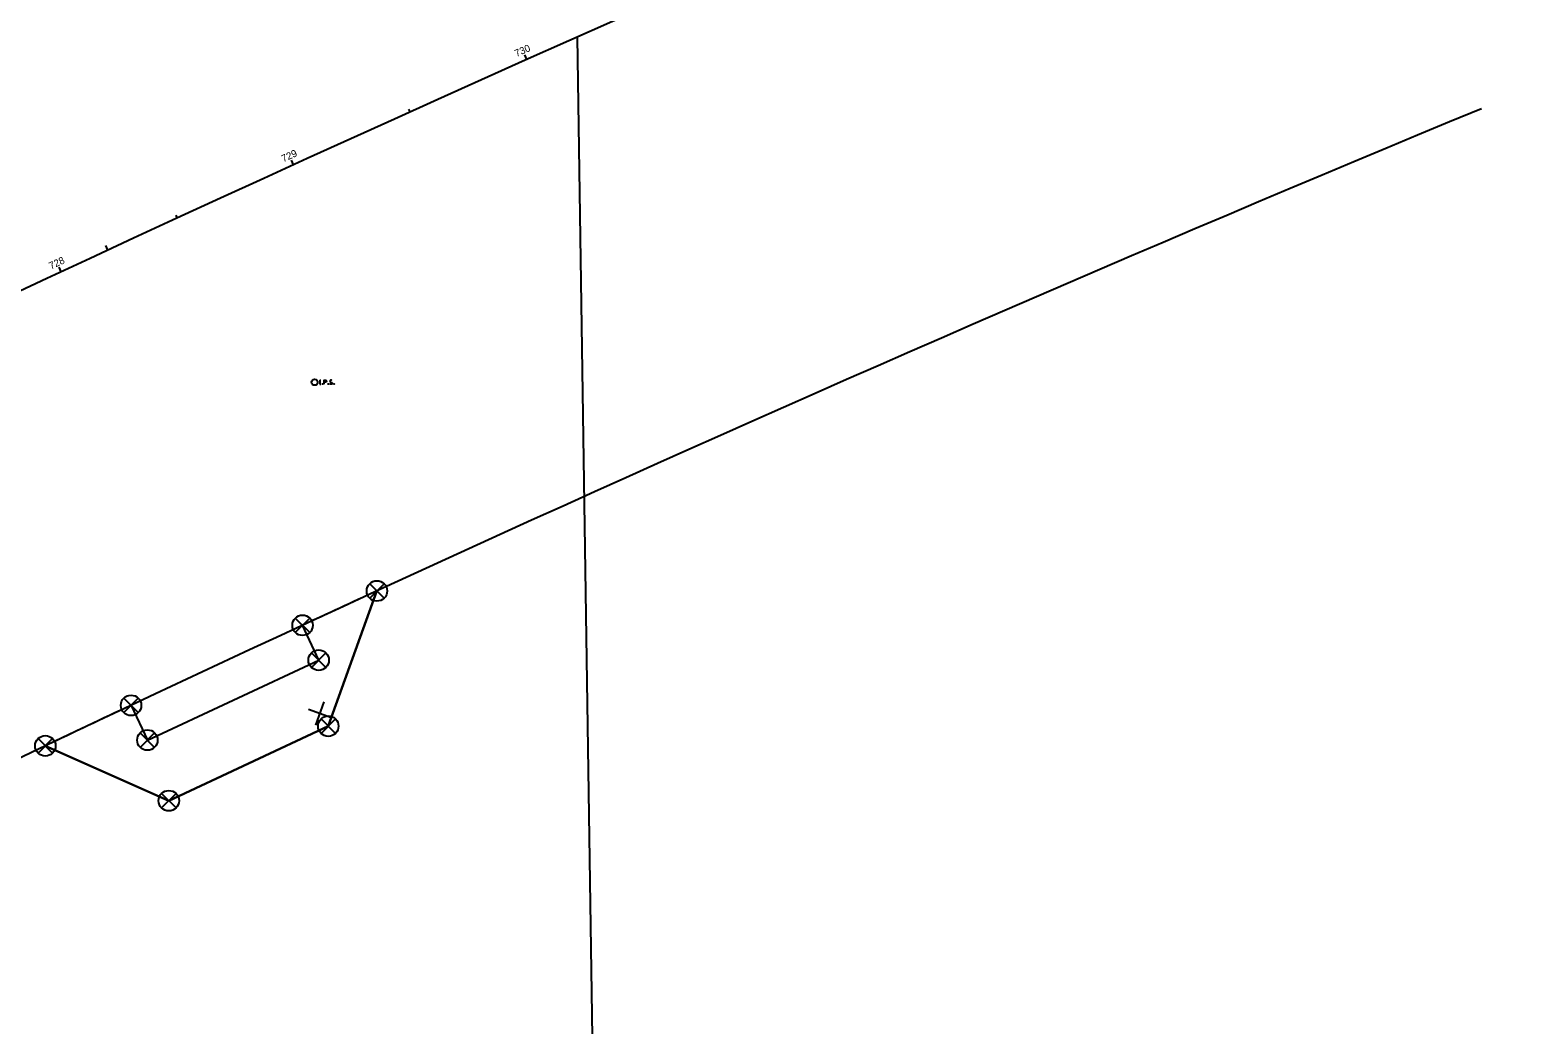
# Model space of a CAD drawing. Extents: x 197895 to 201888, y 454260 to 456995.
# Drawn here: x 201279 to 201868, y 456346 to 456735 of the extents above; entities that cross this region are included whole.
import ezdxf

# ---------------------------------------------------------------- set-up
doc = ezdxf.new("R2010")
doc.units = 0
for name, color, linetype in [('Default', 7, 'Continuous'), ('PF_P_Grade_Line', 7, 'Continuous'), ('PF_X_Ground_Line', 7, 'Continuous'), ('PV_X_EOP', 7, 'Continuous'), ('RD_X_GR_Rt', 7, 'Continuous'), ('RW_X_CL_100_Stations', 7, 'Continuous'), ('RW_X_Esmt_CH', 7, 'Continuous'), ('SC_Scratch1', 7, 'Continuous'), ('SH_Text', 7, 'Continuous'), ('SV_X_Void_Area', 7, 'Continuous'), ('VG_P_Text', 7, 'Continuous')]:
    doc.layers.add(name, color=color, linetype=linetype)

msp = doc.modelspace()

# ---------------------------------------------------------------- linework, layer by layer
at = {"layer": 'Default'}
for p, q in [((201308.11, 456650.4), (201308.96, 456648.59)), ((201411.39, 456518.27), (201417.05, 456512.61)), ((201411.39, 456512.61), (201417.05, 456518.27)), ((201414.22, 456515.44), (201414.22, 456515.44)), ((201382.33, 456504.86), (201387.99, 456499.2)), ((201382.33, 456499.2), (201387.99, 456504.86)), ((201385.16, 456502.03), (201385.16, 456502.03)), ((201388.63, 456491.25), (201394.29, 456485.59)), ((201388.63, 456485.59), (201394.29, 456491.25)), ((201391.46, 456488.42), (201391.46, 456488.42)), ((201315.28, 456473.56), (201320.94, 456467.9)), ((201315.28, 456467.9), (201320.94, 456473.56)), ((201318.11, 456470.73), (201318.11, 456470.73)), ((201392.39, 456465.43), (201398.05, 456459.78)), ((201392.39, 456459.78), (201398.05, 456465.43)), ((201395.22, 456462.61), (201395.22, 456462.61)), ((201281.78, 456457.73), (201287.43, 456452.08)), ((201281.78, 456452.08), (201287.43, 456457.73)), ((201321.67, 456459.99), (201327.33, 456454.33)), ((201321.67, 456454.33), (201327.33, 456459.99)), ((201324.5, 456457.16), (201324.5, 456457.16)), ((201284.61, 456454.9), (201284.61, 456454.9)), ((201330.04, 456436.29), (201335.69, 456430.64)), ((201330.04, 456430.64), (201335.69, 456436.29)), ((201332.86, 456433.47), (201332.86, 456433.47))]:
    msp.add_line(p, q, dxfattribs=at)
for centre in [(201414.22, 456515.44), (201385.16, 456502.03), (201391.46, 456488.42), (201318.11, 456470.73), (201324.5, 456457.16), (201395.22, 456462.61), (201284.61, 456454.9), (201332.86, 456433.47)]:
    msp.add_circle(centre, 4, dxfattribs=at)
at = {"layer": 'PF_P_Grade_Line'}
msp.add_circle((201284.61, 456454.9), 0.05, dxfattribs=at)
at = {"layer": 'PF_X_Ground_Line'}
for points in [[(201391.88, 456597.81), (201392.24, 456597.81)], [(201392.06, 456596.21), (201392.06, 456597.81)], [(201393.02, 456596.42), (201393.07, 456596.42), (201393.11, 456596.4), (201393.14, 456596.35), (201393.14, 456596.28), (201393.11, 456596.23), (201393.07, 456596.21), (201393.02, 456596.21), (201392.98, 456596.23), (201392.95, 456596.28), (201392.95, 456596.35), (201392.98, 456596.4), (201393.02, 456596.42)], [(201393.62, 456596.21), (201393.62, 456597.81), (201394.15, 456597.81), (201394.21, 456597.79), (201394.29, 456597.77), (201394.32, 456597.74), (201394.35, 456597.72), (201394.4, 456597.66), (201394.43, 456597.59), (201394.45, 456597.49), (201394.45, 456597.34), (201394.44, 456597.29), (201394.42, 456597.22), (201394.37, 456597.13), (201394.33, 456597.09), (201394.3, 456597.06), (201394.24, 456597.04), (201394.15, 456597.03), (201393.62, 456597.03)], [(201395.27, 456596.42), (201395.32, 456596.42), (201395.35, 456596.4), (201395.39, 456596.35), (201395.39, 456596.28), (201395.35, 456596.23), (201395.32, 456596.21), (201395.27, 456596.21), (201395.23, 456596.23), (201395.2, 456596.28), (201395.2, 456596.35), (201395.23, 456596.4), (201395.27, 456596.42)], [(201396.63, 456597.69), (201396.61, 456597.72), (201396.58, 456597.74), (201396.48, 456597.78), (201396.36, 456597.81), (201396.27, 456597.81), (201396.24, 456597.81), (201396.09, 456597.77), (201395.97, 456597.69), (201395.89, 456597.59), (201395.87, 456597.49), (201395.87, 456597.42), (201395.89, 456597.32), (201395.98, 456597.23), (201396.59, 456596.85), (201396.64, 456596.8), (201396.67, 456596.75), (201396.69, 456596.67), (201396.69, 456596.6), (201396.68, 456596.52), (201396.67, 456596.47), (201396.64, 456596.41), (201396.62, 456596.36), (201396.6, 456596.32), (201396.57, 456596.28), (201396.53, 456596.26), (201396.49, 456596.23), (201396.46, 456596.22), (201396.36, 456596.21), (201396.2, 456596.21), (201396.1, 456596.23), (201395.96, 456596.32), (201395.87, 456596.4)], [(201397.45, 456596.42), (201397.5, 456596.42), (201397.54, 456596.4), (201397.57, 456596.35), (201397.57, 456596.28), (201397.54, 456596.23), (201397.5, 456596.21), (201397.45, 456596.21), (201397.42, 456596.23), (201397.38, 456596.28), (201397.38, 456596.35), (201397.42, 456596.4), (201397.45, 456596.42)], [(201391.88, 456596.21), (201392.24, 456596.21)]]:
    msp.add_lwpolyline(points, dxfattribs=at)
msp.add_circle((201389.86, 456597.01), 1.2, dxfattribs=at)
at = {"layer": 'PV_X_EOP'}
msp.add_line((201492.53, 456731.9), (201504.39, 455930.45), dxfattribs=at)
at = {"layer": 'RD_X_GR_Rt'}
for p, q in [((201414.22, 456515.44), (201395.22, 456462.61)), ((201391.46, 456488.42), (201385.16, 456502.03)), ((201324.5, 456457.16), (201391.46, 456488.42)), ((201318.11, 456470.73), (201324.5, 456457.16)), ((201395.22, 456462.61), (201332.86, 456433.47)), ((201332.86, 456433.47), (201284.61, 456454.9))]:
    msp.add_line(p, q, dxfattribs=at)
for start, end in [(114.697117, 114.848504), (115.198504, 115.373784)]:
    msp.add_arc((206475.15, 445510.73), 12112.67, start, end, dxfattribs=at)
at = {"layer": 'RW_X_CL_100_Stations'}
for p, q in [((201472.8, 456723.12), (201471.99, 456724.94)), ((201427.18, 456702.65), (201426.69, 456703.74)), ((201381.64, 456682), (201380.81, 456683.82)), ((201336.19, 456661.17), (201335.69, 456662.25)), ((201290.83, 456640.14), (201289.98, 456641.96))]:
    msp.add_line(p, q, dxfattribs=at)
at = {"layer": 'RW_X_Esmt_CH'}
for p, q in [((201391.46, 456488.42), (201385.16, 456502.03)), ((201324.5, 456457.16), (201391.46, 456488.42)), ((201318.11, 456470.73), (201324.5, 456457.16))]:
    msp.add_line(p, q, dxfattribs=at)
at = {"layer": 'SC_Scratch1'}
for p, q in [((201396.53, 456465.88), (201387.44, 456469.18)), ((201390.33, 456462.98), (201393.64, 456472.08))]:
    msp.add_line(p, q, dxfattribs=at)
at = {"layer": 'SH_Text'}
msp.add_arc((206475.15, 445510.73), 12277.67, 112.039489, 134.330526, dxfattribs=at)
at = {"layer": 'SV_X_Void_Area'}
for p, q in [((201395.22, 456462.61), (201414.22, 456515.44)), ((201332.86, 456433.47), (201395.22, 456462.61)), ((201284.61, 456454.9), (201332.86, 456433.47))]:
    msp.add_line(p, q, dxfattribs=at)
at = {"layer": 'VG_P_Text'}
msp.add_arc((206475.15, 445510.73), 12112.67, 112.468785, 116.55179, dxfattribs=at)

# ---------------------------------------------------------------- texts
at = {"layer": 'RW_X_CL_100_Stations'}
for s, rotation, p in [('730', 24.04378, (201468.8, 456724.07)), ('729', 24.51045, (201377.67, 456682.94)), ('728', 24.97712, (201286.82, 456641.04))]:
    msp.add_text(s, height=2.8, rotation=rotation, dxfattribs=at).set_placement(p)

doc.saveas('drawing.dxf')
